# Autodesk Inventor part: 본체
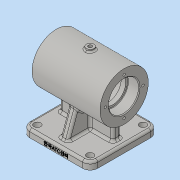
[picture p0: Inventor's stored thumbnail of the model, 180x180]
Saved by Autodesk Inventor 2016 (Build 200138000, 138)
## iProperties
Created: 2019-06
Part Number: 본체
Material: 일반
Document SubType Name: Modeling
Designer: Administrator
Density: 1 g/cm^3
Appearance: 기본값
Mass: 226.064 g
Surface Area: 622.717 cm^2
Volume: 226.064 cm^3
Author: Administrator
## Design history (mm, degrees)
sketch "스케치1"
  geometry: L1 (-45, -45)-(45, -45); L2 (45, -45)-(45, 45); L3 (45, 45)-(-45, 45); L4 (-45, 45)-(-45, -45); L5 (-45, -45)-(45, 45); L6 (45, -45)-(-45, 45); 1 further point
  constraints: 12 end point, 2 midpoint, 2 parallel, 1 horizontal, 1 perpendicular
  dimensions: "d0" = 90 distance of L3.end L2.end; "d1" = 90 distance of L2.end L1.end
extrude "돌출1" new body sketch "스케치1" distance "d2" = 10; taper "d3" = 0 deg
sketch "스케치2"
  geometry: L1 (45, 65)-(-45, 65); L2 (-45, 0)-(45, 0) reference; L3 (45, 65)-(45, 97); L4 (45, 97)-(-45, 97); L5 (-45, 97)-(-45, 65); 2 further points
  constraints: 8 end point, 2 perpendicular, 1 horizontal, 1 midpoint, 1 vertical, 1 vertical alignment
  dimensions: "d4" = 65 distance between parallel lines of L2 L1; "d5" = 90 distance of L1.start L1.end; "d6" = 64 diameter of L4 L1
revolve "회전1" sketch "스케치2" stored, may be unused: angle "d7" = 90 deg
sketch "스케치3"
  geometry: L1 (-45, 10)-(45, 10) reference; L2 (35, 10)-(-35, 10); L3 (-35, 10)-(-35, 23.349); L4 (35, 23.349)-(35, 10); L5 (-45, 0)-(45, 0) reference; 3 further points
  constraints: 6 end point, 2 midpoint, 1 horizontal, 1 parallel, 1 perpendicular, 1 point on line, 1 vertical alignment
  dimensions: "d8" = 70 distance between parallel lines of L3 L4
feature "리브1" sketch "스케치3" dims "d9" = 1, "d10" = 10, "d11" = 0, "d12" = 0, "d13" = 1, "d14" = 1
sketch "스케치5"
  geometry: L1 (45, 10)-(-45, 10) reference; L2 (-35, 10)-(-27.102, 31.698); L3 (-45, 0)-(-45, 10) reference; 1 further point
  constraints: 2 end point, 1 point on line
  dimensions: "d19" = 110 deg angle of L1 L2; "d20" = 10 distance from line of L3 L2.start
feature "리브2" sketch "스케치5" dims "d21" = 1, "d22" = 10, "d23" = 0, "d24" = 0, "d25" = 1, "d26" = 1
sketch "스케치6"
  geometry: L1 (45, 33)-(45, 97) reference; L2 (45, 65)-(-45, 65); L3 (-45, 33)-(-45, 97) reference; L4 (45, 65)-(45, 85); L5 (45, 85)-(30, 85); L6 (30, 85)-(30, 82); L7 (30, 82)-(24, 82); L8 (24, 82)-(24, 90); L9 (24, 90)-(-24, 90); L10 (-24, 90)-(-24, 82); L11 (-24, 82)-(-30, 82); L12 (-30, 82)-(-30, 85); L13 (-30, 85)-(-45, 85); L14 (-45, 85)-(-45, 65); 1 further point
  constraints: 24 end point, 6 perpendicular, 6 point on line, 2 midpoint, 1 collinear, 1 horizontal
  dimensions: "d27" = 40 diameter of L5 L2; "d28" = 34 diameter of L7 L2; "d29" = 50 diameter of L9 L2; "d30" = 15 distance of L4.end L5.end; "d31" = 15 distance of L12.end L13.end; "d32" = 6 distance of L6.end L7.end; "d33" = 6 distance of L10.end L11.end
revolve "회전2" sketch "스케치6" stored, may be unused: angle "d34" = 90 deg
sketch "스케치7"
  geometry: L1 (65, -45)-(65, 45) reference; C1 r 17 at (0, 0) reference; 3 further points
  constraints: 1 horizontal alignment, 1 midpoint
  dimensions: "d35" = 25 distance of C1.centre point (-25, 0)
hole "구멍1" sketch "스케치7" at (-25, 0) diameter "d36" = 3.242; stored, may be unused: countersink angle "d40" = 90 deg, drill point angle "d42" = 118 deg; dims "d37" = 7, "d38" = 4, "d39" = 2, "d41" = 9
node "작업 평면1"
sketch "스케치8"
  geometry: C1 r 5 at (0, 0); 1 further point
  constraints: 1 centre point, 1 coincident
  dimensions: "d47" = 10 diameter of C1
extrude "돌출2" join sketch "스케치8" stored distance "d48" = 10; taper "d49" = 0 deg
hole "구멍2" diameter "d52" = 4.917; stored, may be unused: countersink angle "d56" = 90 deg, drill point angle "d58" = 118 deg; dims "d50" = 10, "d51" = 10, "d53" = 12, "d54" = 4, "d55" = 2, "d57" = 17.1
hole "구멍3" diameter "d61" = 9; stored, may be unused: countersink angle "d65" = 90 deg, drill point angle "d67" = 118 deg; dims "d59" = 10, "d60" = 10, "d62" = 12, "d63" = 4, "d64" = 2, "d66" = 17.1
sketch "스케치9"
  geometry: L1 (22.155, 40)-(-22.155, 40); L2 (-40, 22.155)-(-40, -22.155); L3 (-22.155, -40)-(22.155, -40); L4 (40, -22.155)-(40, 22.155); L5 (40, 40)-(-40, -40); L6 (-40, 40)-(40, -40); L7 (45, -45)-(-45, -45) reference; L8 (0, -45)-(0, 45); L9 (-45, 45)-(45, 45) reference; L10 (45, 45)-(45, -45) reference; L11 (45, 0)-(-45, 0); L12 (-45, -20)-(-45, 20) reference; C1 r 2.458 at (0, 0) reference; C2 r 4.5 at (35, -35) reference; A1 r 10 centre (35, -35) between (36.538, -25.119) and (25.119, -36.538); A2 r 10 centre (-35, -35) between (-25.119, -36.538) and (-36.538, -25.119); A3 r 10 centre (-35, 35) between (-36.538, 25.119) and (-25.119, 36.538); A4 r 10 centre (35, 35) between (25.119, 36.538) and (36.538, 25.119); A5 r 3 centre (22.155, 37) between (25.119, 36.538) and (22.155, 40); A6 r 3 centre (37, 22.155) between (40, 22.155) and (36.538, 25.119); A7 r 3 centre (37, -22.155) between (36.538, -25.119) and (40, -22.155); A8 r 3 centre (22.155, -37) between (22.155, -40) and (25.119, -36.538); A9 r 3 centre (-22.155, -37) between (-25.119, -36.538) and (-22.155, -40); A10 r 3 centre (-37, -22.155) between (-40, -22.155) and (-36.538, -25.119); A11 r 3 centre (-37, 22.155) between (-36.538, 25.119) and (-40, 22.155); A12 r 3 centre (-22.155, 37) between (-22.155, 40) and (-25.119, 36.538); 9 further points
  constraints: 32 point on circle, 16 end point, 16 tangent, 12 centre point, 8 point on line, 7 equal radius, 6 midpoint, 3 symmetric about line, 2 parallel, 1 coincident, 1 horizontal, 1 perpendicular, 3 other
  dimensions: "d68" = 80 distance of L6.end L5.end; "d69" = 80 distance of L5.end L6.start; "d70" = 10 radius of A1; "d71" = 3 radius of A5
extrude "돌출4" cut sketch "스케치9" distance "d74" = 5; taper "d75" = 0 deg
fillet "모깎기1" dims "d76" = 10
fillet "모깎기2" dims "d77" = 3, "d78" = 0.6
chamfer "모따기1" distance "d79" = 1; stored, may be unused: second distance "d80" = 2, angle "d81" = 45 deg
fillet "모깎기3" dims "d82" = 2
fillet "모깎기4" dims "d83" = 3
fillet "모깎기5" dims "d84" = 3
fillet "모깎기6" dims "d85" = 3
sketch "스케치10"
  geometry: L1 (-10, 7)-(-10, 0) reference; 2 further points
  constraints: 1 other
  dimensions: "d86" = 45 distance from line of L1 point (35, 4); "d87" = 4 distance of point (35, 0) point (35, 4)
feature "엠보싱1" sketch "스케치10" dims "d0" = 90, "d1" = 90, "d88" = 0.5, "d89" = 0
feature "분할1"
node "솔리드1"
mirror "대칭1"
pattern_circular "원형 패턴1" dims angle "d44" = 360 deg
mirror "대칭2"
mirror "대칭3"
mirror "대칭4"
